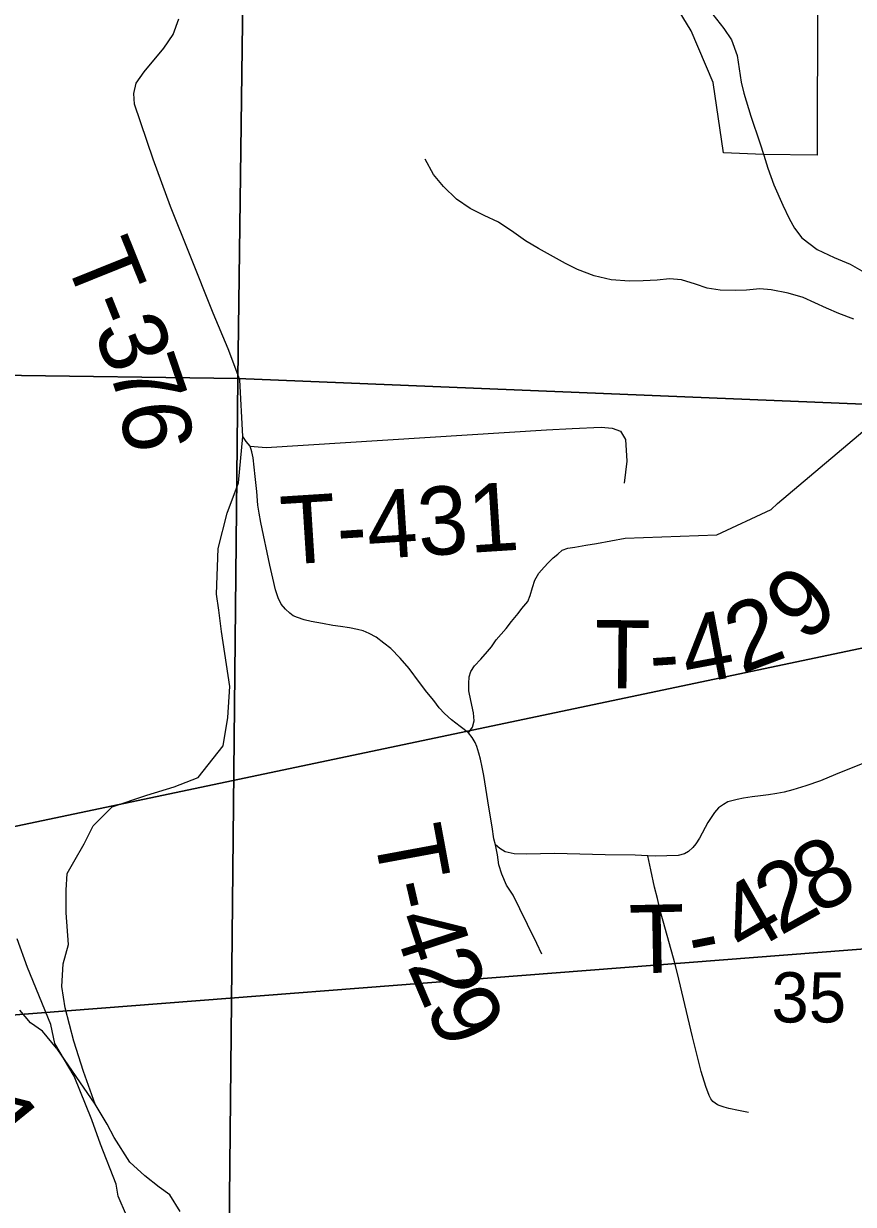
# Model space of a CAD drawing. Extents: x 0 to 34, y 0 to 22.
# Drawn here: x 6.268 to 6.959, y 17.402 to 18.385 of the extents above; entities that cross this region are included whole.
import ezdxf

# ---------------------------------------------------------------- set-up
doc = ezdxf.new("R2010")
doc.units = 0
for name, color, linetype in [('GM_X_Corporation', 7, 'Continuous'), ('GM_X_County_Road', 7, 'Continuous'), ('GM_X_Minor_River', 7, 'Continuous'), ('GM_X_Section', 7, 'Continuous'), ('GM_X_Section_Text', 7, 'Continuous'), ('GM_X_Township_Road', 7, 'Continuous'), ('GM_X_Township_Road_Text', 7, 'Continuous'), ('SC_Shading1', 7, 'Continuous'), ('SH_Data', 7, 'Continuous')]:
    doc.layers.add(name, color=color, linetype=linetype)

msp = doc.modelspace()

# ---------------------------------------------------------------- linework, layer by layer
at = {"layer": 'GM_X_Corporation'}
for p, q in [((6.9292, 18.41704), (6.92899, 18.27525)), ((6.82398, 18.37903), (6.80302, 18.41335)), ((6.84247, 18.33587), (6.82398, 18.37903)), ((6.8511, 18.2773), (6.84247, 18.33587)), ((6.88434, 18.27584), (6.8511, 18.2773)), ((6.92899, 18.27525), (6.88434, 18.27584))]:
    msp.add_line(p, q, dxfattribs=at)
at = {"layer": 'GM_X_County_Road'}
for p, q in [((6.84208, 18.39265), (6.85125, 18.38076)), ((6.85125, 18.38076), (6.85757, 18.37152)), ((6.85757, 18.37152), (6.86223, 18.35824)), ((6.86223, 18.35824), (6.86411, 18.34726)), ((6.86411, 18.34726), (6.86564, 18.33614)), ((6.86564, 18.33614), (6.86786, 18.32711)), ((6.86786, 18.32711), (6.87377, 18.30785)), ((6.87377, 18.30785), (6.88121, 18.28561)), ((6.88121, 18.28561), (6.88446, 18.27551)), ((6.88446, 18.27551), (6.88802, 18.26449)), ((6.88802, 18.26449), (6.89288, 18.25065)), ((6.89288, 18.25065), (6.90032, 18.23369)), ((6.90032, 18.23369), (6.9056, 18.22257)), ((6.9056, 18.22257), (6.91012, 18.21472)), ((6.91012, 18.21472), (6.91624, 18.20666)), ((6.91624, 18.20666), (6.92895, 18.19693)), ((6.92895, 18.19693), (6.94306, 18.19026)), ((6.94306, 18.19026), (6.95655, 18.18449)), ((6.95655, 18.18449), (6.96815, 18.17795))]:
    msp.add_line(p, q, dxfattribs=at)
at = {"layer": 'GM_X_Minor_River'}
for p, q in [((6.60937, 18.25935), (6.60251, 18.27207)), ((6.61766, 18.24934), (6.60937, 18.25935)), ((6.62864, 18.23865), (6.61766, 18.24934)), ((6.6399, 18.23101), (6.62864, 18.23865)), ((6.65148, 18.22528), (6.6399, 18.23101)), ((6.66345, 18.21957), (6.65148, 18.22528)), ((6.67626, 18.21085), (6.66345, 18.21957)), ((6.68598, 18.20392), (6.67626, 18.21085)), ((6.69682, 18.19779), (6.68598, 18.20392)), ((6.71926, 18.18518), (6.69682, 18.19779)), ((6.7293, 18.18017), (6.71926, 18.18518)), ((6.74315, 18.17489), (6.7293, 18.18017)), ((6.75733, 18.17153), (6.74315, 18.17489)), ((6.77256, 18.17049), (6.75733, 18.17153)), ((6.78396, 18.17085), (6.77256, 18.17049)), ((6.79573, 18.17122), (6.78396, 18.17085)), ((6.80597, 18.1723), (6.79573, 18.17122)), ((6.81588, 18.17147), (6.80597, 18.1723)), ((6.82777, 18.16804), (6.81588, 18.17147)), ((6.83738, 18.16453), (6.82777, 18.16804)), ((6.84808, 18.16297), (6.83738, 18.16453)), ((6.86063, 18.1626), (6.84808, 18.16297)), ((6.87013, 18.1629), (6.86063, 18.1626)), ((6.88112, 18.164), (6.87013, 18.1629)), ((6.89065, 18.16316), (6.88112, 18.164)), ((6.9048, 18.16056), (6.89065, 18.16316)), ((6.91746, 18.15677), (6.9048, 18.16056)), ((6.9271, 18.15251), (6.91746, 18.15677)), ((6.93675, 18.14787), (6.9271, 18.15251)), ((6.94715, 18.14363), (6.93675, 18.14787)), ((6.95947, 18.13868), (6.94715, 18.14363)), ((6.27125, 17.59887), (6.26253, 17.62271)), ((6.29058, 17.5516), (6.27125, 17.59887)), ((6.29387, 17.53567), (6.29058, 17.5516)), ((6.31021, 17.50852), (6.29387, 17.53567)), ((6.32481, 17.47221), (6.31021, 17.50852)), ((6.33196, 17.45177), (6.32481, 17.47221)), ((6.345, 17.41848), (6.33196, 17.45177)), ((6.34668, 17.40861), (6.345, 17.41848)), ((6.35376, 17.39235), (6.34668, 17.40861))]:
    msp.add_line(p, q, dxfattribs=at)
at = {"layer": 'GM_X_Section'}
for p, q in [((6.45993, 19.12233), (6.44653, 18.08952)), ((6.44653, 18.08952), (6.45993, 19.12233)), ((6.44653, 18.08952), (5.51984, 18.10239)), ((5.51984, 18.10239), (6.44653, 18.08952)), ((6.44653, 18.08952), (6.43657, 17.11137)), ((6.43657, 17.11137), (6.44653, 18.08952)), ((7.45701, 18.04776), (6.44653, 18.08952)), ((6.44653, 18.08952), (7.45701, 18.04776))]:
    msp.add_line(p, q, dxfattribs=at)
at = {"layer": 'GM_X_Township_Road'}
for p, q in [((6.39255, 18.37586), (6.39714, 18.38901)), ((6.38469, 18.36455), (6.39255, 18.37586)), ((6.36829, 18.34483), (6.38469, 18.36455)), ((6.36181, 18.33536), (6.36829, 18.34483)), ((6.35986, 18.32682), (6.36181, 18.33536)), ((6.36046, 18.31774), (6.35986, 18.32682)), ((6.3759, 18.27213), (6.36046, 18.31774)), ((6.39039, 18.23269), (6.3759, 18.27213)), ((6.40679, 18.19182), (6.39039, 18.23269)), ((6.4258, 18.14383), (6.40679, 18.19182)), ((6.43839, 18.11413), (6.4258, 18.14383)), ((6.44813, 18.08823), (6.43839, 18.11413)), ((6.45066, 18.04112), (6.44813, 18.08823)), ((6.89603, 17.98525), (7.0002, 18.07328)), ((6.46999, 18.03192), (6.70343, 18.04657)), ((6.70343, 18.04657), (6.72492, 18.04774)), ((6.72492, 18.04774), (6.74902, 18.04876)), ((6.74902, 18.04876), (6.75825, 18.04799)), ((6.75825, 18.04799), (6.76517, 18.04543)), ((6.76517, 18.04543), (6.76927, 18.03863)), ((6.44698, 18.00266), (6.45066, 18.04112)), ((6.45337, 18.03703), (6.45066, 18.04112)), ((6.45668, 18.03305), (6.45337, 18.03703)), ((6.45817, 18.02841), (6.45668, 18.03305)), ((6.45668, 18.03305), (6.46999, 18.03192)), ((6.76927, 18.03863), (6.77043, 18.02069)), ((6.45916, 18.02328), (6.45817, 18.02841)), ((6.46098, 18.00771), (6.45916, 18.02328)), ((6.77043, 18.02069), (6.76813, 18.00214)), ((6.46231, 17.99529), (6.46098, 18.00771)), ((6.43743, 17.97713), (6.44698, 18.00266)), ((6.46314, 17.98402), (6.46231, 17.99529)), ((6.46413, 17.97723), (6.46314, 17.98402)), ((6.89067, 17.98034), (6.89603, 17.98525)), ((6.43003, 17.94771), (6.43743, 17.97713)), ((6.46546, 17.96945), (6.46413, 17.97723)), ((6.8454, 17.95934), (6.89067, 17.98034)), ((6.47306, 17.93407), (6.46546, 17.96945)), ((6.74518, 17.95214), (6.76901, 17.95636)), ((6.76901, 17.95636), (6.8454, 17.95934)), ((6.42867, 17.90991), (6.43003, 17.94771)), ((6.71287, 17.94326), (6.71659, 17.94639)), ((6.71659, 17.94639), (6.72136, 17.94803)), ((6.72136, 17.94803), (6.72716, 17.94907)), ((6.72716, 17.94907), (6.73625, 17.95056)), ((6.73625, 17.95056), (6.74518, 17.95214)), ((6.70165, 17.93218), (6.70483, 17.93596)), ((6.70483, 17.93596), (6.709, 17.94013)), ((6.709, 17.94013), (6.71287, 17.94326)), ((6.47556, 17.92324), (6.47306, 17.93407)), ((6.69387, 17.92158), (6.69702, 17.92721)), ((6.69702, 17.92721), (6.70165, 17.93218)), ((6.47788, 17.9133), (6.47556, 17.92324)), ((6.69006, 17.90883), (6.69188, 17.91529)), ((6.69188, 17.91529), (6.69387, 17.92158)), ((6.43061, 17.89646), (6.42867, 17.90991)), ((6.47987, 17.90667), (6.47788, 17.9133)), ((6.48252, 17.90154), (6.47987, 17.90667)), ((6.68791, 17.90369), (6.69006, 17.90883)), ((6.43276, 17.87873), (6.43061, 17.89646)), ((6.486, 17.8974), (6.48252, 17.90154)), ((6.48964, 17.89408), (6.486, 17.8974)), ((6.67996, 17.89375), (6.6831, 17.89789)), ((6.6831, 17.89789), (6.68791, 17.90369)), ((6.49246, 17.89176), (6.48964, 17.89408)), ((6.4961, 17.89044), (6.49246, 17.89176)), ((6.50157, 17.88845), (6.4961, 17.89044)), ((6.50753, 17.88713), (6.50157, 17.88845)), ((6.5168, 17.88531), (6.50753, 17.88713)), ((6.66985, 17.88133), (6.67432, 17.88713)), ((6.67432, 17.88713), (6.67996, 17.89375)), ((6.43977, 17.83294), (6.43276, 17.87873)), ((6.52542, 17.88382), (6.5168, 17.88531)), ((6.53204, 17.88282), (6.52542, 17.88382)), ((6.5395, 17.88166), (6.53204, 17.88282)), ((6.54596, 17.8805), (6.5395, 17.88166)), ((6.55092, 17.87918), (6.54596, 17.8805)), ((6.55573, 17.87719), (6.55092, 17.87918)), ((6.56169, 17.87404), (6.55573, 17.87719)), ((6.66174, 17.87189), (6.66588, 17.87653)), ((6.66588, 17.87653), (6.66985, 17.88133)), ((6.56799, 17.86907), (6.56169, 17.87404)), ((6.57395, 17.86444), (6.56799, 17.86907)), ((6.65445, 17.86195), (6.65776, 17.86609)), ((6.65776, 17.86609), (6.66174, 17.87189)), ((6.58157, 17.85665), (6.57395, 17.86444)), ((6.58919, 17.84804), (6.58157, 17.85665)), ((6.64882, 17.85582), (6.65445, 17.86195)), ((6.5978, 17.83628), (6.58919, 17.84804)), ((6.64053, 17.84539), (6.64352, 17.85003)), ((6.64352, 17.85003), (6.64882, 17.85582)), ((6.60393, 17.82833), (6.5978, 17.83628)), ((6.63871, 17.83545), (6.63904, 17.84091)), ((6.63904, 17.84091), (6.64053, 17.84539)), ((6.43821, 17.80722), (6.43977, 17.83294)), ((6.60956, 17.8212), (6.60393, 17.82833)), ((6.63888, 17.82932), (6.63871, 17.83545)), ((6.64053, 17.82137), (6.63888, 17.82932)), ((6.6142, 17.81524), (6.60956, 17.8212)), ((6.64269, 17.81093), (6.64053, 17.82137)), ((6.43432, 17.78346), (6.43821, 17.80722)), ((6.6185, 17.81044), (6.6142, 17.81524)), ((6.62447, 17.80514), (6.6185, 17.81044)), ((6.64328, 17.80434), (6.64269, 17.81093)), ((6.63159, 17.79951), (6.62447, 17.80514)), ((6.63855, 17.79437), (6.63159, 17.79951)), ((6.63855, 17.79437), (6.64202, 17.79917)), ((6.64202, 17.79917), (6.64328, 17.80434)), ((6.64153, 17.79056), (6.63855, 17.79437)), ((6.64401, 17.78642), (6.64153, 17.79056)), ((6.41342, 17.75728), (6.43432, 17.78346)), ((6.6455, 17.78294), (6.64401, 17.78642)), ((6.64716, 17.77748), (6.6455, 17.78294)), ((6.64848, 17.77234), (6.64716, 17.77748)), ((6.64981, 17.76572), (6.64848, 17.77234)), ((6.96932, 17.76953), (6.95872, 17.76555)), ((6.6513, 17.75892), (6.64981, 17.76572)), ((6.65312, 17.74832), (6.6513, 17.75892)), ((6.94431, 17.75959), (6.93172, 17.75445)), ((6.95872, 17.76555), (6.94431, 17.75959)), ((6.37056, 17.74246), (6.39351, 17.74933)), ((6.39351, 17.74933), (6.41342, 17.75728)), ((6.65561, 17.73242), (6.65312, 17.74832)), ((6.91946, 17.75015), (6.9087, 17.747)), ((6.93172, 17.75445), (6.91946, 17.75015)), ((6.34159, 17.73283), (6.37056, 17.74246)), ((6.86232, 17.73888), (6.8547, 17.7369)), ((6.86762, 17.74004), (6.86232, 17.73888)), ((6.87474, 17.74104), (6.86762, 17.74004)), ((6.88187, 17.74186), (6.87474, 17.74104)), ((6.88849, 17.74269), (6.88187, 17.74186)), ((6.89545, 17.74385), (6.88849, 17.74269)), ((6.90158, 17.74501), (6.89545, 17.74385)), ((6.9087, 17.747), (6.90158, 17.74501)), ((6.32599, 17.71689), (6.34159, 17.73283)), ((6.65826, 17.71603), (6.65561, 17.73242)), ((6.8436, 17.72812), (6.83806, 17.71959)), ((6.84692, 17.73176), (6.8436, 17.72812)), ((6.85089, 17.73474), (6.84692, 17.73176)), ((6.8547, 17.7369), (6.85089, 17.73474)), ((6.83806, 17.71959), (6.831, 17.7066)), ((6.31844, 17.70179), (6.32599, 17.71689)), ((6.65958, 17.70609), (6.65826, 17.71603)), ((6.30991, 17.68702), (6.31844, 17.70179)), ((6.66115, 17.70101), (6.65958, 17.70609)), ((6.66455, 17.69814), (6.66115, 17.70101)), ((6.66267, 17.69286), (6.66115, 17.70101)), ((6.82538, 17.6988), (6.82174, 17.69549)), ((6.82803, 17.70178), (6.82538, 17.6988)), ((6.831, 17.7066), (6.82803, 17.70178)), ((6.66389, 17.68439), (6.66267, 17.69286)), ((6.66919, 17.69532), (6.66455, 17.69814)), ((6.67664, 17.6935), (6.66919, 17.69532)), ((6.68691, 17.69333), (6.67664, 17.6935)), ((6.71027, 17.69383), (6.68691, 17.69333)), ((6.75234, 17.69284), (6.71027, 17.69383)), ((6.77735, 17.69256), (6.75234, 17.69284)), ((6.78792, 17.69201), (6.77735, 17.69256)), ((6.79441, 17.69168), (6.78792, 17.69201)), ((6.79048, 17.68024), (6.78792, 17.69201)), ((6.81313, 17.69217), (6.79441, 17.69168)), ((6.81843, 17.6935), (6.81313, 17.69217)), ((6.82174, 17.69549), (6.81843, 17.6935)), ((6.30433, 17.67717), (6.30991, 17.68702)), ((6.66621, 17.6766), (6.66389, 17.68439)), ((6.79353, 17.66593), (6.79048, 17.68024)), ((6.30334, 17.66339), (6.30433, 17.67717)), ((6.67035, 17.66749), (6.66621, 17.6766)), ((6.30334, 17.64435), (6.30334, 17.66339)), ((6.67565, 17.65905), (6.67035, 17.66749)), ((6.79588, 17.65634), (6.79353, 17.66593)), ((6.68128, 17.64778), (6.67565, 17.65905)), ((6.79855, 17.64531), (6.79588, 17.65634)), ((6.30531, 17.6181), (6.30334, 17.64435)), ((6.68774, 17.63486), (6.68128, 17.64778)), ((6.8006, 17.63747), (6.79855, 17.64531)), ((6.69552, 17.6188), (6.68774, 17.63486)), ((6.81072, 17.60163), (6.8006, 17.63747)), ((6.30104, 17.60202), (6.30531, 17.6181)), ((6.69958, 17.60992), (6.69552, 17.6188)), ((6.29973, 17.58298), (6.30104, 17.60202)), ((6.81384, 17.58923), (6.81072, 17.60163)), ((6.30268, 17.56526), (6.29973, 17.58298)), ((6.82503, 17.54121), (6.81384, 17.58923)), ((6.2738, 17.55278), (6.26494, 17.56329)), ((6.30991, 17.53769), (6.30268, 17.56526)), ((6.28365, 17.54589), (6.2738, 17.55278)), ((6.29535, 17.53186), (6.28365, 17.54589)), ((6.29596, 17.53112), (6.29535, 17.53186)), ((6.31778, 17.51241), (6.30991, 17.53769)), ((6.83233, 17.51237), (6.82503, 17.54121)), ((6.32763, 17.48517), (6.29596, 17.53112)), ((6.32763, 17.48517), (6.31778, 17.51241)), ((6.83621, 17.49997), (6.83233, 17.51237)), ((6.83911, 17.49228), (6.83621, 17.49997)), ((6.84032, 17.48955), (6.83911, 17.49228)), ((6.33747, 17.4686), (6.32763, 17.48517)), ((6.84207, 17.48734), (6.84032, 17.48955)), ((6.84405, 17.48589), (6.84207, 17.48734)), ((6.84588, 17.4846), (6.84405, 17.48589)), ((6.84816, 17.48361), (6.84588, 17.4846)), ((6.85151, 17.48262), (6.84816, 17.48361)), ((6.85547, 17.48156), (6.85151, 17.48262)), ((6.86338, 17.47973), (6.85547, 17.48156)), ((6.8719, 17.47821), (6.86338, 17.47973)), ((6.34338, 17.45724), (6.33747, 17.4686)), ((6.35631, 17.43691), (6.34338, 17.45724)), ((6.36907, 17.42545), (6.35631, 17.43691)), ((6.3809, 17.41603), (6.36907, 17.42545)), ((6.38976, 17.40956), (6.3809, 17.41603)), ((6.39826, 17.3957), (6.38976, 17.40956))]:
    msp.add_line(p, q, dxfattribs=at)
at = {"layer": 'SC_Shading1'}
msp.add_lwpolyline([(10.22402, 18.55077), (10.22402, 17.86726), (5.07832, 17.46758)], close=True, dxfattribs=at)
at = {"layer": 'SH_Data'}
msp.add_lwpolyline([(10.22402, 18.55077), (5.07832, 17.46758), (10.22402, 17.86726)], dxfattribs=at)

# ---------------------------------------------------------------- texts
at = {"layer": 'GM_X_Section_Text'}
msp.add_text('35', height=0.041856, rotation=0.00001, dxfattribs=at).set_placement((6.89088, 17.55315))
at = {"layer": 'GM_X_Township_Road_Text'}
for s, height, rotation, p in [('T', 0.05682, 291.92397, (6.30111, 18.19072)), ('-', 0.05682, 291.77677, (6.31697, 18.15133)), ('3', 0.05682, 291.18584, (6.32557, 18.1298)), ('7', 0.05682, 288.92043, (6.33801, 18.09773)), ('6', 0.05682, 275.84885, (6.34863, 18.06796)), ('T-431', 0.056818, 3.64643, (6.48382, 17.93425)), ('9', 0.05682, 42.74308, (6.91898, 17.86799)), ('2', 0.05682, 20.68486, (6.86607, 17.84316)), ('4', 0.05682, 10.67627, (6.82128, 17.83376)), ('T', 0.05682, 359.43859, (6.74341, 17.83156)), ('-', 0.05682, 3.7909, (6.79061, 17.83128)), ('T', 0.05682, 280.51133, (6.5592, 17.71153)), ('8', 0.05682, 28.50413, (6.92848, 17.64198)), ('2', 0.05682, 29.19815, (6.89808, 17.62499)), ('-', 0.05682, 283.02657, (6.5675, 17.66708)), ('4', 0.05682, 29.85682, (6.86788, 17.60765)), ('T', 0.05682, 1.07575, (6.77283, 17.59405)), ('4', 0.05682, 288.05704, (6.57422, 17.63911)), ('-', 0.05682, 11.33885, (6.82634, 17.59605)), ('2', 0.05682, 293.0875, (6.58698, 17.60074)), ('9', 0.05682, 295.60274, (6.60183, 17.56607)), ('1', 0.05682, 309.15061, (6.21684, 17.46676))]:
    msp.add_text(s, height=height, rotation=rotation, dxfattribs=at).set_placement(p)

doc.saveas('drawing.dxf')
